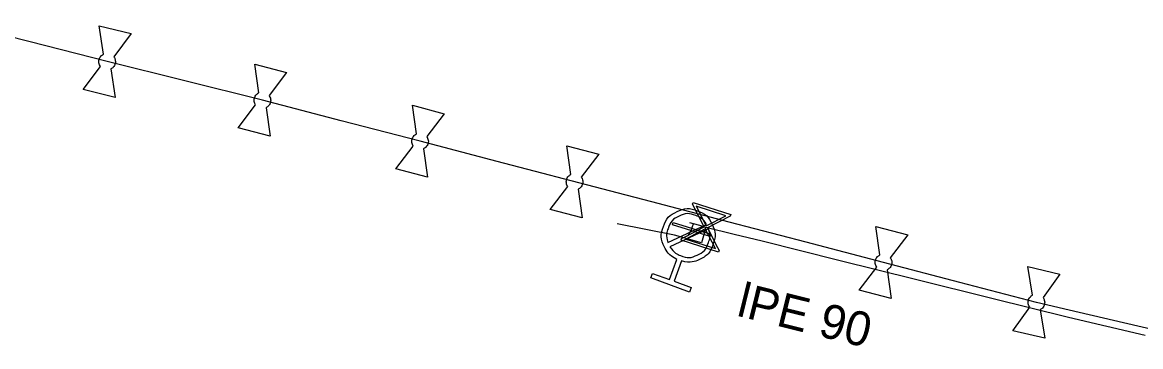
# Model space of a CAD drawing. Extents: x -638315 to -636370, y -1116147 to -1115110.
# Drawn here: x -637253.73 to -637211.24, y -1116048.78 to -1116036.46 of the extents above; entities that cross this region are included whole.
import ezdxf

# ---------------------------------------------------------------- set-up
doc = ezdxf.new("R2010")
doc.units = 0
for name, color, linetype in [('Default', 7, 'Continuous'), ('VP Hydrant', 7, 'Continuous'), ('VP Lomový bod', 7, 'Continuous'), ('VP Přípojka', 7, 'Continuous'), ('VP Řad', 7, 'Continuous'), ('VP Řad - popis', 7, 'Continuous'), ('VP Šoupě', 7, 'Continuous')]:
    doc.layers.add(name, color=color, linetype=linetype)

msp = doc.modelspace()

# ---------------------------------------------------------------- linework, layer by layer
at = {"layer": 'Default'}
for points in [[(-637250.767, -1116038.131), (-637250.796, -1116038.089), (-637250.811, -1116038.037), (-637250.833, -1116037.954), (-637250.813, -1116037.874), (-637250.793, -1116037.795), (-637250.735, -1116037.734), (-637250.698, -1116037.694), (-637250.651, -1116037.671)], [(-637250.255, -1116037.769), (-637250.224, -1116037.812), (-637250.21, -1116037.865), (-637250.187, -1116037.946), (-637250.207, -1116038.026), (-637250.227, -1116038.105), (-637250.286, -1116038.168), (-637250.322, -1116038.207), (-637250.37, -1116038.23)], [(-637244.868, -1116039.599), (-637244.898, -1116039.556), (-637244.912, -1116039.504), (-637244.933, -1116039.42), (-637244.912, -1116039.341), (-637244.892, -1116039.262), (-637244.833, -1116039.202), (-637244.795, -1116039.162), (-637244.748, -1116039.139)], [(-637244.353, -1116039.242), (-637244.323, -1116039.285), (-637244.309, -1116039.338), (-637244.287, -1116039.42), (-637244.308, -1116039.499), (-637244.328, -1116039.578), (-637244.389, -1116039.64), (-637244.425, -1116039.679), (-637244.473, -1116039.702)], [(-637238.879, -1116041.158), (-637238.908, -1116041.115), (-637238.922, -1116041.064), (-637238.943, -1116040.98), (-637238.922, -1116040.901), (-637238.902, -1116040.822), (-637238.843, -1116040.761), (-637238.805, -1116040.722), (-637238.757, -1116040.699)], [(-637238.363, -1116040.803), (-637238.332, -1116040.846), (-637238.319, -1116040.899), (-637238.297, -1116040.98), (-637238.318, -1116041.059), (-637238.338, -1116041.138), (-637238.399, -1116041.201), (-637238.436, -1116041.239), (-637238.483, -1116041.262)], [(-637233.008, -1116042.699), (-637233.038, -1116042.656), (-637233.052, -1116042.604), (-637233.073, -1116042.52), (-637233.052, -1116042.441), (-637233.032, -1116042.362), (-637232.973, -1116042.302), (-637232.935, -1116042.262), (-637232.888, -1116042.239)], [(-637232.493, -1116042.342), (-637232.463, -1116042.385), (-637232.449, -1116042.438), (-637232.427, -1116042.52), (-637232.448, -1116042.599), (-637232.468, -1116042.678), (-637232.529, -1116042.74), (-637232.565, -1116042.779), (-637232.613, -1116042.802)], [(-637228.857, -1116045.465), (-637229.185, -1116045.314), (-637229.338, -1116044.982), (-637229.511, -1116044.607), (-637229.369, -1116044.216), (-637229.227, -1116043.827), (-637228.852, -1116043.653), (-637228.477, -1116043.479), (-637228.086, -1116043.621), (-637227.699, -1116043.762), (-637227.523, -1116044.137), (-637227.348, -1116044.511), (-637227.49, -1116044.9), (-637227.632, -1116045.291), (-637228.006, -1116045.467), (-637228.337, -1116045.625), (-637228.684, -1116045.527)], [(-637227.735, -1116044.135), (-637227.879, -1116043.898), (-637228.151, -1116043.799), (-637228.467, -1116043.684), (-637228.772, -1116043.826), (-637229.077, -1116043.967), (-637229.192, -1116044.285), (-637229.291, -1116044.556), (-637229.202, -1116044.819)], [(-637229.125, -1116044.985), (-637228.982, -1116045.226), (-637228.707, -1116045.326), (-637228.389, -1116045.442), (-637228.085, -1116045.3), (-637227.781, -1116045.158), (-637227.665, -1116044.84), (-637227.565, -1116044.565), (-637227.658, -1116044.301)], [(-637221.269, -1116045.758), (-637221.298, -1116045.715), (-637221.312, -1116045.664), (-637221.333, -1116045.58), (-637221.312, -1116045.501), (-637221.292, -1116045.422), (-637221.233, -1116045.361), (-637221.195, -1116045.322), (-637221.147, -1116045.299)], [(-637220.753, -1116045.402), (-637220.723, -1116045.446), (-637220.709, -1116045.499), (-637220.687, -1116045.58), (-637220.708, -1116045.659), (-637220.728, -1116045.738), (-637220.789, -1116045.801), (-637220.825, -1116045.839), (-637220.873, -1116045.862)], [(-637215.454, -1116047.285), (-637215.484, -1116047.243), (-637215.5, -1116047.192), (-637215.523, -1116047.109), (-637215.504, -1116047.029), (-637215.486, -1116046.949), (-637215.429, -1116046.887), (-637215.392, -1116046.847), (-637215.345, -1116046.823)], [(-637214.948, -1116046.916), (-637214.916, -1116046.958), (-637214.901, -1116047.011), (-637214.877, -1116047.091), (-637214.896, -1116047.171), (-637214.914, -1116047.251), (-637214.973, -1116047.315), (-637215.009, -1116047.354), (-637215.056, -1116047.378)]]:
    msp.add_open_spline(points, degree=3, dxfattribs=at)
at = {"layer": 'VP Hydrant'}
for points in [[(-637229.202, -1116044.819), (-637227.735, -1116044.135)], [(-637227.658, -1116044.301), (-637229.125, -1116044.985)], [(-637228.684, -1116045.527), (-637228.965, -1116046.298), (-637228.317, -1116046.534), (-637228.38, -1116046.707), (-637229.848, -1116046.172), (-637229.785, -1116046), (-637229.138, -1116046.235), (-637228.857, -1116045.465)]]:
    msp.add_lwpolyline(points, dxfattribs=at)
at = {"layer": 'VP Lomový bod'}
for points in [[(-637250.651, -1116037.671), (-637250.814, -1116036.586), (-637249.601, -1116036.888), (-637250.255, -1116037.769)], [(-637250.206, -1116039.314), (-637251.419, -1116039.012), (-637250.767, -1116038.131)], [(-637250.37, -1116038.23), (-637250.206, -1116039.314)], [(-637244.748, -1116039.139), (-637244.9, -1116038.053), (-637243.69, -1116038.368), (-637244.353, -1116039.242)], [(-637244.32, -1116040.787), (-637245.53, -1116040.472), (-637244.868, -1116039.599)], [(-637244.473, -1116039.702), (-637244.32, -1116040.787)], [(-637238.757, -1116040.699), (-637238.907, -1116039.612), (-637237.698, -1116039.93), (-637238.363, -1116040.803)], [(-637238.333, -1116042.348), (-637239.542, -1116042.03), (-637238.879, -1116041.158)], [(-637238.483, -1116041.262), (-637238.333, -1116042.348)], [(-637232.888, -1116042.239), (-637233.04, -1116041.153), (-637231.83, -1116041.468), (-637232.493, -1116042.342)], [(-637232.46, -1116043.887), (-637233.67, -1116043.572), (-637233.008, -1116042.699)], [(-637232.613, -1116042.802), (-637232.46, -1116043.887)], [(-637221.147, -1116045.299), (-637221.298, -1116044.213), (-637220.089, -1116044.529), (-637220.753, -1116045.402)], [(-637220.722, -1116046.947), (-637221.931, -1116046.631), (-637221.269, -1116045.758)], [(-637220.873, -1116045.862), (-637220.722, -1116046.947)], [(-637215.345, -1116046.823), (-637215.525, -1116045.741), (-637214.307, -1116046.025), (-637214.948, -1116046.916)], [(-637214.875, -1116048.459), (-637216.093, -1116048.175), (-637215.454, -1116047.285)], [(-637215.056, -1116047.378), (-637214.875, -1116048.459)]]:
    msp.add_lwpolyline(points, dxfattribs=at)
at = {"layer": 'VP Přípojka'}
for points in [[(-637227.76, -1116044.25), (-637227.92, -1116044.84), (-637228.95, -1116044.55), (-637231.13, -1116044.12)], [(-637228.43, -1116044.56), (-637228.365, -1116044.445), (-637228.3, -1116044.33), (-637228.265, -1116044.22), (-637228.23, -1116044.11)]]:
    msp.add_lwpolyline(points, dxfattribs=at)
at = {"layer": 'VP Řad'}
for points in [[(-637209.33, -1116048.47), (-637212.265, -1116047.785), (-637213.952, -1116047.391), (-637215.2, -1116047.1), (-637218.105, -1116046.34), (-637221.01, -1116045.58), (-637223.945, -1116044.815), (-637226.88, -1116044.05), (-637229.815, -1116043.285), (-637231.417, -1116042.866), (-637235.685, -1116041.75), (-637238.62, -1116040.98), (-637241.615, -1116040.2), (-637244.61, -1116039.42), (-637247.56, -1116038.685), (-637250.51, -1116037.95), (-637253.43, -1116037.205), (-637256.35, -1116036.46)], [(-637211.07, -1116048.36), (-637213.98, -1116047.68), (-637216.89, -1116046.955), (-637219.8, -1116046.23), (-637222.71, -1116045.505), (-637225.62, -1116044.78), (-637226.69, -1116044.515), (-637227.76, -1116044.25), (-637227.995, -1116044.18), (-637228.23, -1116044.11), (-637228.37, -1116044.08)]]:
    msp.add_lwpolyline(points, dxfattribs=at)
at = {"layer": 'VP Šoupě'}
for points in [[(-637227.274, -1116045.193), (-637228.703, -1116044.736), (-637228.683, -1116044.673), (-637228.567, -1116044.618), (-637227.82, -1116044.232), (-637228.266, -1116043.37), (-637228.246, -1116043.307), (-637226.817, -1116043.764), (-637226.837, -1116043.827), (-637227.702, -1116044.27), (-637227.316, -1116045.016), (-637227.254, -1116045.13), (-637227.274, -1116045.193)], [(-637228.129, -1116043.443), (-637227.742, -1116044.192), (-637226.995, -1116043.806), (-637228.129, -1116043.443)], [(-637229.004, -1116044.066), (-637227.569, -1116044.504), (-637227.596, -1116044.594), (-637229.031, -1116044.156), (-637229.004, -1116044.066)], [(-637227.395, -1116045.056), (-637227.78, -1116044.31), (-637228.524, -1116044.695), (-637227.395, -1116045.056)]]:
    msp.add_lwpolyline(points, dxfattribs=at)

# ---------------------------------------------------------------- texts
at = {"layer": 'VP Řad - popis'}
msp.add_text('lPE 90', height=1.3, rotation=346.0898, dxfattribs=at).set_placement((-637226.632, -1116047.599))

doc.saveas('drawing.dxf')
